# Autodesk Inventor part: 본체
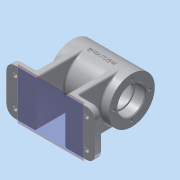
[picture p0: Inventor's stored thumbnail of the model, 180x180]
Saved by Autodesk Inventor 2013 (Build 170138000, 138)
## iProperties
Created: 2017-02
Part Number: 본체
Material: 알루미늄 6061
Document SubType Name: Modeling
Designer: Administrator
Density: 2.71 g/cm^3
Mass: 355.586 g
Surface Area: 423.837 cm^2
Volume: 131.213 cm^3
Author: Administrator
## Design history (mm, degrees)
sketch "스케치2"
  geometry: C1 r 27 at (0, 0); 1 further point
  constraints: 1 centre point, 1 coincident
  dimensions: "d0" = 54 diameter of C1
extrude "돌출1" new body sketch "스케치2" stored distance "d1" = 70; taper "d2" = 0 deg
sketch "스케치3"
  geometry: C1 r 16 at (0, 0); 1 further point
  constraints: 1 centre point, 1 coincident
  dimensions: "d3" = 32 diameter of C1
extrude "돌출2" cut sketch "스케치3" distance "d4" = 12; taper "d5" = 0 deg
sketch "스케치4"
  geometry: C1 r 27 at (0, 0) reference; C2 r 14 at (0, 0); 1 further point
  constraints: 1 centre point, 1 coincident
  dimensions: "d6" = 28 diameter of C2
extrude "돌출3" cut sketch "스케치4" distance "d7" = 3; taper "d8" = 0 deg
sketch "스케치6"
  geometry: C1 r 22 at (0, 0); 1 further point
  constraints: 1 centre point, 1 coincident
  dimensions: "d10" = 44 diameter of C1
extrude "돌출4" cut sketch "스케치6" distance "d11" = 40; taper "d12" = 0 deg
node "작업 평면1"
sketch "스케치7"
  geometry: L1 (5, 26.533)-(5, 32); L2 (5, 32)-(0, 32); L3 (0, 32)-(0, 27); A1 r 27 centre (0, 0) between (0, 27) and (5, 26.533) reference; 3 further points
  constraints: 6 end point, 2 point on circle, 1 parallel, 1 vertical alignment, 1 other
  dimensions: "d14" = 5 distance of L1.end L2.end; "d16" = 5 distance edge to line of A1 L2
revolve "회전1" sketch "스케치7" stored, may be unused: angle "d17" = 90 deg
hole "구멍1" diameter "d20" = 5.188; stored, may be unused: countersink angle "d24" = 90 deg, drill point angle "d26" = 118 deg; dims "d21" = 6, "d22" = 4, "d23" = 2, "d25" = 20, "d27" = 10, "d28" = 10
node "작업 평면2"
sketch "스케치8"
  geometry: L1 (0, 0)-(-14.705, -22.644); L2 (-14.705, -22.644)-(-16.339, -25.16); L3 (-16.339, -25.16)-(-11.307, -28.428); L4 (-11.307, -28.428)-(-9.306, -25.346); L5 (-9.306, -25.346)-(-14.338, -22.078); L6 (0, 0)-(0, -27); C1 r 16 at (0, 0) reference; C2 r 22 at (0, 0) reference; A1 r 27 centre (0, 0) between (-14.705, -22.644) and (-9.306, -25.346) reference
  constraints: 12 end point, 3 point on circle, 2 perpendicular, 1 collinear, 1 parallel, 1 point on line, 1 vertical
  dimensions: "d98" = 6 distance between parallel lines of L4 L2; "d100" = 30 distance from line of C1.centre L3; "d101" = 33 deg angle of L1 L6
  node "투영된 루프4"
node "작업 평면3"
sketch "스케치9"
  geometry: L1 (35, 27)-(-35, 27) reference; L2 (-35, 27)-(-35, -27) reference; L3 (35, -27)-(-35, -27) reference; L4 (35, -27)-(35, 27) reference; L5 (52, -17)-(52, 17); L6 (-52, 17)-(-52, -17); L7 (-52, -27)-(52, 27); L8 (52, -27)-(-52, 27); L9 (-17, 27)-(-17, -27); L10 (17, -27)-(17, 27); L11 (42, 27)-(17, 27); L12 (-17, 27)-(-42, 27); L13 (-42, -27)-(-17, -27); L14 (17, -27)-(42, -27); A1 r 10 centre (-42, 17) between (-42, 27) and (-52, 17); A2 r 10 centre (-42, -17) between (-52, -17) and (-42, -27); A3 r 10 centre (42, -17) between (42, -27) and (52, -17); A4 r 10 centre (42, 17) between (52, 17) and (42, 27); 1 further point
  constraints: 20 end point, 12 tangent, 8 point on circle, 5 parallel, 5 perpendicular, 4 centre point, 4 point on line, 3 equal radius, 2 horizontal, 2 midpoint
  dimensions: "d45" = 104 distance of L7.end L8.end; "d47" = 54 distance of L8.start L7.end; "d48" = 17 distance from line of L9 point (0, 0); "d49" = 17 distance from line of L10 point (0, 0); "d50" = 10 radius of A1
extrude "돌출5" join sketch "스케치9" distance "d51" = 8; taper "d52" = 0 deg
hole "구멍3" diameter "d55" = 5; stored, may be unused: countersink angle "d59" = 90 deg, drill point angle "d61" = 120 deg; dims "d53" = 10, "d54" = 10, "d56" = 6, "d57" = 9, "d58" = 3, "d60" = 30
sketch "스케치10"
  geometry: L1 (44, 8)-(10, 8) reference; L2 (0, 0)-(0, 8) reference; L3 (54, 0)-(54, 8) reference; L4 (-10.8, 0)-(64.8, 0) reference; L5 (0, 8)-(0, 60); L6 (54, 8)-(54, 60); L7 (5.5, 8)-(14.5, 8) reference; L8 (10, 8)-(0, 8) reference; L9 (39.5, 8)-(48.5, 8) reference; L10 (54, 8)-(44, 8) reference; A1 r 27 centre (27, 60) between (0, 60) and (54, 60) reference; 1 further point
  constraints: 4 end point, 2 point on circle, 1 parallel, 1 tangent
extrude "돌출6" join sketch "스케치10" distance "d68" = 8; taper "d69" = 0 deg
sketch "스케치11"
  geometry: A1 r 21 centre (0, 0) between (0, 21) and (-21, 0); 3 further points
  constraints: 4 point on circle, 1 centre point, 1 coincident
  dimensions: "d70" = 42 diameter of A1
hole "구멍4" sketch "스케치11" at (0, 21), (-21, 0), (0, -21), (21, 0.13) diameter "d72" = 3.242; stored, may be unused: countersink angle "d76" = 90 deg, drill point angle "d78" = 120 deg; dims "d73" = 8, "d74" = 4, "d75" = 2, "d77" = 10
fillet "모깎기1" dims "d79" = 2
chamfer "모따기1" distance "d80" = 1; stored, may be unused: second distance "d81" = 2, angle "d82" = 45 deg
fillet "모깎기2" dims "d83" = 0.3, "d84" = 2
node "작업 평면4"
sketch "스케치12"
  geometry: L1 (-35, 27)-(-35, -27) reference; L2 (-35, 27)-(35, 27) reference; 2 further points
  constraints: 1 other
  dimensions: "d86" = 27 distance from line of point (0, 0) L2; "d87" = 35 distance from line of L1 point (0, 0)
feature "엠보싱1" sketch "스케치12" dims "d11" = 40, "d12" = 0, "d88" = 0.5, "d89" = 0
revolve "회전3" stored, may be unused: angle "d102" = 90 deg
hole "구멍5" diameter "d105" = 5.188; stored, may be unused: countersink angle "d109" = 90 deg, drill point angle "d111" = 0 deg; dims "d106" = 6, "d107" = 4, "d108" = 2, "d110" = 30, "d112" = 10, "d113" = 10
node "솔리드1"
mirror "대칭1"
pattern_linear "직사각형 패턴1" dims "d64" = 84, "d67" = 34
mirror "대칭2"
mirror "대칭3"
node "투영된 루프1"
node "투영된 루프3"
other parameters: "d13" = -25, "d29" = -35
